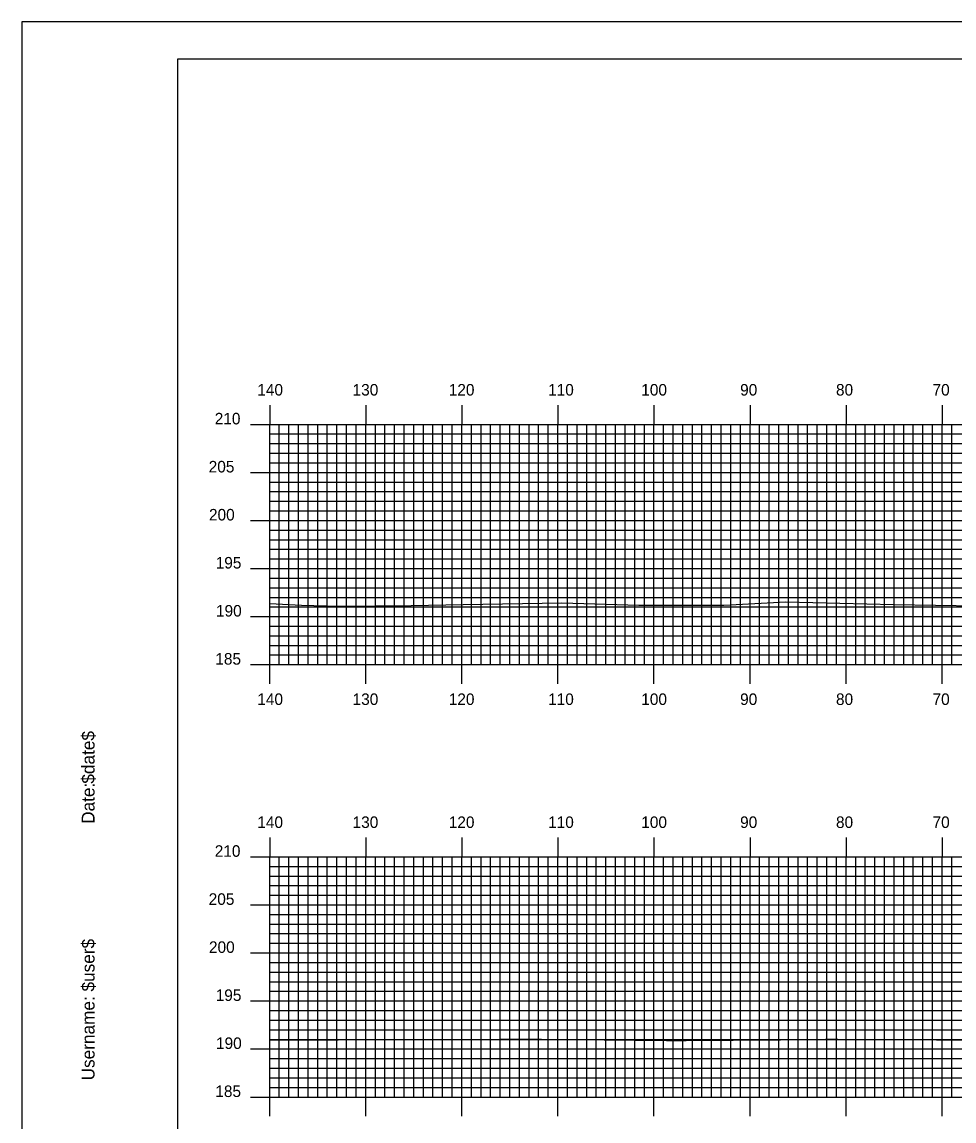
# Model space of a CAD drawing. Extents: x 1814915 to 1815259, y 442591 to 442811.
# Drawn here: x 1814915.2 to 1815012.3, y 442696.2 to 442810.5 of the extents above; entities that cross this region are included whole.
import ezdxf

# ---------------------------------------------------------------- set-up
doc = ezdxf.new("R2010")
doc.units = 0
for name, color, linetype in [('BORDER', 7, 'Continuous'), ('H_V ANNOTATION', 7, 'Continuous'), ('MAJOR', 7, 'Continuous'), ('MINOR', 7, 'Continuous'), ('PLOT BOUNDARY', 7, 'Continuous'), ('S_Roadway_Centerline', 7, 'Continuous')]:
    doc.layers.add(name, color=color, linetype=linetype)

msp = doc.modelspace()

# ---------------------------------------------------------------- linework, layer by layer
at = {"layer": 'BORDER'}
msp.add_lwpolyline([(1814931.42, 442596.67), (1815251.42, 442596.67), (1815251.42, 442806.67), (1814931.42, 442806.67)], close=True, dxfattribs=at)
at = {"layer": 'MAJOR'}
for p, q in [((1814941.02, 442770.67), (1814941.02, 442768.67)), ((1814951.02, 442770.67), (1814951.02, 442768.67)), ((1814961.02, 442770.67), (1814961.02, 442768.67)), ((1814971.02, 442770.67), (1814971.02, 442768.67)), ((1814981.02, 442770.67), (1814981.02, 442768.67)), ((1814991.02, 442770.67), (1814991.02, 442768.67)), ((1815001.02, 442770.67), (1815001.02, 442768.67)), ((1815011.02, 442770.67), (1815011.02, 442768.67)), ((1814939.02, 442768.67), (1814941.02, 442768.67)), ((1814941.02, 442768.67), (1815221.02, 442768.67)), ((1814941.02, 442743.67), (1814941.02, 442768.67)), ((1814941.02, 442743.67), (1814941.02, 442768.67)), ((1814941.02, 442768.67), (1815221.02, 442768.67)), ((1814951.02, 442743.67), (1814951.02, 442768.67)), ((1814961.02, 442743.67), (1814961.02, 442768.67)), ((1814971.02, 442743.67), (1814971.02, 442768.67)), ((1814981.02, 442743.67), (1814981.02, 442768.67)), ((1814991.02, 442743.67), (1814991.02, 442768.67)), ((1815001.02, 442743.67), (1815001.02, 442768.67)), ((1815011.02, 442743.67), (1815011.02, 442768.67)), ((1814939.02, 442763.67), (1814941.02, 442763.67)), ((1814941.02, 442763.67), (1815221.02, 442763.67)), ((1814939.02, 442758.67), (1814941.02, 442758.67)), ((1814941.02, 442758.67), (1815221.02, 442758.67)), ((1814939.02, 442753.67), (1814941.02, 442753.67)), ((1814941.02, 442753.67), (1815221.02, 442753.67)), ((1814939.02, 442748.67), (1814941.02, 442748.67)), ((1814941.02, 442748.67), (1815221.02, 442748.67)), ((1814939.02, 442743.67), (1814941.02, 442743.67)), ((1814941.02, 442743.67), (1815221.02, 442743.67)), ((1814941.02, 442743.67), (1815221.02, 442743.67)), ((1814941.02, 442741.66), (1814941.02, 442743.67)), ((1814951.02, 442741.66), (1814951.02, 442743.67)), ((1814961.02, 442741.66), (1814961.02, 442743.67)), ((1814971.02, 442741.66), (1814971.02, 442743.67)), ((1814981.02, 442741.66), (1814981.02, 442743.67)), ((1814991.02, 442741.66), (1814991.02, 442743.67)), ((1815001.02, 442741.66), (1815001.02, 442743.67)), ((1815011.02, 442741.66), (1815011.02, 442743.67)), ((1814941.02, 442725.67), (1814941.02, 442723.67)), ((1814951.02, 442725.67), (1814951.02, 442723.67)), ((1814961.02, 442725.67), (1814961.02, 442723.67)), ((1814971.02, 442725.67), (1814971.02, 442723.67)), ((1814981.02, 442725.67), (1814981.02, 442723.67)), ((1814991.02, 442725.67), (1814991.02, 442723.67)), ((1815001.02, 442725.67), (1815001.02, 442723.67)), ((1815011.02, 442725.67), (1815011.02, 442723.67)), ((1814939.02, 442723.67), (1814941.02, 442723.67)), ((1814941.02, 442723.67), (1815221.02, 442723.67)), ((1814941.02, 442698.67), (1814941.02, 442723.67)), ((1814941.02, 442698.67), (1814941.02, 442723.67)), ((1814941.02, 442723.67), (1815221.02, 442723.67)), ((1814951.02, 442698.67), (1814951.02, 442723.67)), ((1814961.02, 442698.67), (1814961.02, 442723.67)), ((1814971.02, 442698.67), (1814971.02, 442723.67)), ((1814981.02, 442698.67), (1814981.02, 442723.67)), ((1814991.02, 442698.67), (1814991.02, 442723.67)), ((1815001.02, 442698.67), (1815001.02, 442723.67)), ((1815011.02, 442698.67), (1815011.02, 442723.67)), ((1814939.02, 442718.67), (1814941.02, 442718.67)), ((1814941.02, 442718.67), (1815221.02, 442718.67)), ((1814939.02, 442713.67), (1814941.02, 442713.67)), ((1814941.02, 442713.67), (1815221.02, 442713.67)), ((1814939.02, 442708.67), (1814941.02, 442708.67)), ((1814941.02, 442708.67), (1815221.02, 442708.67)), ((1814939.02, 442703.67), (1814941.02, 442703.67)), ((1814941.02, 442703.67), (1815221.02, 442703.67)), ((1814939.02, 442698.67), (1814941.02, 442698.67)), ((1814941.02, 442698.67), (1815221.02, 442698.67)), ((1814941.02, 442698.67), (1815221.02, 442698.67)), ((1814941.02, 442696.66), (1814941.02, 442698.67)), ((1814951.02, 442696.66), (1814951.02, 442698.67)), ((1814961.02, 442696.66), (1814961.02, 442698.67)), ((1814971.02, 442696.66), (1814971.02, 442698.67)), ((1814981.02, 442696.66), (1814981.02, 442698.67)), ((1814991.02, 442696.66), (1814991.02, 442698.67)), ((1815001.02, 442696.66), (1815001.02, 442698.67)), ((1815011.02, 442696.66), (1815011.02, 442698.67))]:
    msp.add_line(p, q, dxfattribs=at)
at = {"layer": 'MINOR'}
for p, q in [((1814941.02, 442743.67), (1814941.02, 442768.67)), ((1814941.02, 442767.67), (1815221.02, 442767.67)), ((1814941.02, 442767.67), (1814943.02, 442767.67)), ((1814942.02, 442743.67), (1814942.02, 442768.67)), ((1814943.02, 442743.67), (1814943.02, 442768.67)), ((1814944.02, 442743.67), (1814944.02, 442768.67)), ((1814945.02, 442743.67), (1814945.02, 442768.67)), ((1814946.02, 442743.67), (1814946.02, 442768.67)), ((1814947.02, 442743.67), (1814947.02, 442768.67)), ((1814948.02, 442743.67), (1814948.02, 442768.67)), ((1814949.02, 442743.67), (1814949.02, 442768.67)), ((1814950.02, 442743.67), (1814950.02, 442768.67)), ((1814952.02, 442743.67), (1814952.02, 442768.67)), ((1814953.02, 442743.67), (1814953.02, 442768.67)), ((1814954.02, 442743.67), (1814954.02, 442768.67)), ((1814955.02, 442743.67), (1814955.02, 442768.67)), ((1814956.02, 442743.67), (1814956.02, 442768.67)), ((1814957.02, 442743.67), (1814957.02, 442768.67)), ((1814958.02, 442743.67), (1814958.02, 442768.67)), ((1814959.02, 442743.67), (1814959.02, 442768.67)), ((1814960.02, 442743.67), (1814960.02, 442768.67)), ((1814962.02, 442743.67), (1814962.02, 442768.67)), ((1814963.02, 442743.67), (1814963.02, 442768.67)), ((1814964.02, 442743.67), (1814964.02, 442768.67)), ((1814965.02, 442743.67), (1814965.02, 442768.67)), ((1814966.02, 442743.67), (1814966.02, 442768.67)), ((1814967.02, 442743.67), (1814967.02, 442768.67)), ((1814968.02, 442743.67), (1814968.02, 442768.67)), ((1814969.02, 442743.67), (1814969.02, 442768.67)), ((1814970.02, 442743.67), (1814970.02, 442768.67)), ((1814972.02, 442743.67), (1814972.02, 442768.67)), ((1814973.02, 442743.67), (1814973.02, 442768.67)), ((1814974.02, 442743.67), (1814974.02, 442768.67)), ((1814975.02, 442743.67), (1814975.02, 442768.67)), ((1814976.02, 442743.67), (1814976.02, 442768.67)), ((1814977.02, 442743.67), (1814977.02, 442768.67)), ((1814978.02, 442743.67), (1814978.02, 442768.67)), ((1814979.02, 442743.67), (1814979.02, 442768.67)), ((1814980.02, 442743.67), (1814980.02, 442768.67)), ((1814982.02, 442743.67), (1814982.02, 442768.67)), ((1814983.02, 442743.67), (1814983.02, 442768.67)), ((1814984.02, 442743.67), (1814984.02, 442768.67)), ((1814985.02, 442743.67), (1814985.02, 442768.67)), ((1814986.02, 442743.67), (1814986.02, 442768.67)), ((1814987.02, 442743.67), (1814987.02, 442768.67)), ((1814988.02, 442743.67), (1814988.02, 442768.67)), ((1814989.02, 442743.67), (1814989.02, 442768.67)), ((1814990.02, 442743.67), (1814990.02, 442768.67)), ((1814992.02, 442743.67), (1814992.02, 442768.67)), ((1814993.02, 442743.67), (1814993.02, 442768.67)), ((1814994.02, 442743.67), (1814994.02, 442768.67)), ((1814995.02, 442743.67), (1814995.02, 442768.67)), ((1814996.02, 442743.67), (1814996.02, 442768.67)), ((1814997.02, 442743.67), (1814997.02, 442768.67)), ((1814998.02, 442743.67), (1814998.02, 442768.67)), ((1814999.02, 442743.67), (1814999.02, 442768.67)), ((1815000.02, 442743.67), (1815000.02, 442768.67)), ((1815002.02, 442743.67), (1815002.02, 442768.67)), ((1815003.02, 442743.67), (1815003.02, 442768.67)), ((1815004.02, 442743.67), (1815004.02, 442768.67)), ((1815005.02, 442743.67), (1815005.02, 442768.67)), ((1815006.02, 442743.67), (1815006.02, 442768.67)), ((1815007.02, 442743.67), (1815007.02, 442768.67)), ((1815008.02, 442743.67), (1815008.02, 442768.67)), ((1815009.02, 442743.67), (1815009.02, 442768.67)), ((1815010.02, 442743.67), (1815010.02, 442768.67)), ((1815012.02, 442743.67), (1815012.02, 442768.67)), ((1814941.02, 442766.67), (1815221.02, 442766.67)), ((1814941.02, 442766.67), (1814943.02, 442766.67)), ((1814941.02, 442765.67), (1815221.02, 442765.67)), ((1814941.02, 442765.67), (1814943.02, 442765.67)), ((1814941.02, 442764.67), (1815221.02, 442764.67)), ((1814941.02, 442764.67), (1814943.02, 442764.67)), ((1814941.02, 442762.67), (1815221.02, 442762.67)), ((1814941.02, 442762.67), (1814943.02, 442762.67)), ((1814941.02, 442761.67), (1815221.02, 442761.67)), ((1814941.02, 442761.67), (1814943.02, 442761.67)), ((1814941.02, 442760.67), (1815221.02, 442760.67)), ((1814941.02, 442760.67), (1814943.02, 442760.67)), ((1814941.02, 442759.67), (1815221.02, 442759.67)), ((1814941.02, 442759.67), (1814943.02, 442759.67)), ((1814941.02, 442757.67), (1815221.02, 442757.67)), ((1814941.02, 442757.67), (1814943.02, 442757.67)), ((1814941.02, 442756.67), (1815221.02, 442756.67)), ((1814941.02, 442756.67), (1814943.02, 442756.67)), ((1814941.02, 442755.67), (1815221.02, 442755.67)), ((1814941.02, 442755.67), (1814943.02, 442755.67)), ((1814941.02, 442754.67), (1815221.02, 442754.67)), ((1814941.02, 442754.67), (1814943.02, 442754.67)), ((1814941.02, 442752.67), (1815221.02, 442752.67)), ((1814941.02, 442752.67), (1814943.02, 442752.67)), ((1814941.02, 442751.67), (1815221.02, 442751.67)), ((1814941.02, 442751.67), (1814943.02, 442751.67)), ((1814941.02, 442750.67), (1815221.02, 442750.67)), ((1814941.02, 442750.67), (1814943.02, 442750.67)), ((1814941.02, 442749.67), (1815221.02, 442749.67)), ((1814941.02, 442749.67), (1814943.02, 442749.67)), ((1814941.02, 442747.67), (1815221.02, 442747.67)), ((1814941.02, 442747.67), (1814943.02, 442747.67)), ((1814941.02, 442746.67), (1815221.02, 442746.67)), ((1814941.02, 442746.67), (1814943.02, 442746.67)), ((1814941.02, 442745.67), (1815221.02, 442745.67)), ((1814941.02, 442745.67), (1814943.02, 442745.67)), ((1814941.02, 442744.67), (1815221.02, 442744.67)), ((1814941.02, 442744.67), (1814943.02, 442744.67)), ((1814942.02, 442698.67), (1814942.02, 442723.67)), ((1814943.02, 442698.67), (1814943.02, 442723.67)), ((1814944.02, 442698.67), (1814944.02, 442723.67)), ((1814945.02, 442698.67), (1814945.02, 442723.67)), ((1814946.02, 442698.67), (1814946.02, 442723.67)), ((1814947.02, 442698.67), (1814947.02, 442723.67)), ((1814948.02, 442698.67), (1814948.02, 442723.67)), ((1814949.02, 442698.67), (1814949.02, 442723.67)), ((1814950.02, 442698.67), (1814950.02, 442723.67)), ((1814952.02, 442698.67), (1814952.02, 442723.67)), ((1814953.02, 442698.67), (1814953.02, 442723.67)), ((1814954.02, 442698.67), (1814954.02, 442723.67)), ((1814955.02, 442698.67), (1814955.02, 442723.67)), ((1814956.02, 442698.67), (1814956.02, 442723.67)), ((1814957.02, 442698.67), (1814957.02, 442723.67)), ((1814958.02, 442698.67), (1814958.02, 442723.67)), ((1814959.02, 442698.67), (1814959.02, 442723.67)), ((1814960.02, 442698.67), (1814960.02, 442723.67)), ((1814962.02, 442698.67), (1814962.02, 442723.67)), ((1814963.02, 442698.67), (1814963.02, 442723.67)), ((1814964.02, 442698.67), (1814964.02, 442723.67)), ((1814965.02, 442698.67), (1814965.02, 442723.67)), ((1814966.02, 442698.67), (1814966.02, 442723.67)), ((1814967.02, 442698.67), (1814967.02, 442723.67)), ((1814968.02, 442698.67), (1814968.02, 442723.67)), ((1814969.02, 442698.67), (1814969.02, 442723.67)), ((1814970.02, 442698.67), (1814970.02, 442723.67)), ((1814972.02, 442698.67), (1814972.02, 442723.67)), ((1814973.02, 442698.67), (1814973.02, 442723.67)), ((1814974.02, 442698.67), (1814974.02, 442723.67)), ((1814975.02, 442698.67), (1814975.02, 442723.67)), ((1814976.02, 442698.67), (1814976.02, 442723.67)), ((1814977.02, 442698.67), (1814977.02, 442723.67)), ((1814978.02, 442698.67), (1814978.02, 442723.67)), ((1814979.02, 442698.67), (1814979.02, 442723.67)), ((1814980.02, 442698.67), (1814980.02, 442723.67)), ((1814982.02, 442698.67), (1814982.02, 442723.67)), ((1814983.02, 442698.67), (1814983.02, 442723.67)), ((1814984.02, 442698.67), (1814984.02, 442723.67)), ((1814985.02, 442698.67), (1814985.02, 442723.67)), ((1814986.02, 442698.67), (1814986.02, 442723.67)), ((1814987.02, 442698.67), (1814987.02, 442723.67)), ((1814988.02, 442698.67), (1814988.02, 442723.67)), ((1814989.02, 442698.67), (1814989.02, 442723.67)), ((1814990.02, 442698.67), (1814990.02, 442723.67)), ((1814992.02, 442698.67), (1814992.02, 442723.67)), ((1814993.02, 442698.67), (1814993.02, 442723.67)), ((1814994.02, 442698.67), (1814994.02, 442723.67)), ((1814995.02, 442698.67), (1814995.02, 442723.67)), ((1814996.02, 442698.67), (1814996.02, 442723.67)), ((1814997.02, 442698.67), (1814997.02, 442723.67)), ((1814998.02, 442698.67), (1814998.02, 442723.67)), ((1814999.02, 442698.67), (1814999.02, 442723.67)), ((1815000.02, 442698.67), (1815000.02, 442723.67)), ((1815002.02, 442698.67), (1815002.02, 442723.67)), ((1815003.02, 442698.67), (1815003.02, 442723.67)), ((1815004.02, 442698.67), (1815004.02, 442723.67)), ((1815005.02, 442698.67), (1815005.02, 442723.67)), ((1815006.02, 442698.67), (1815006.02, 442723.67)), ((1815007.02, 442698.67), (1815007.02, 442723.67)), ((1815008.02, 442698.67), (1815008.02, 442723.67)), ((1815009.02, 442698.67), (1815009.02, 442723.67)), ((1815010.02, 442698.67), (1815010.02, 442723.67)), ((1815012.02, 442698.67), (1815012.02, 442723.67)), ((1814941.02, 442722.67), (1815221.02, 442722.67)), ((1814941.02, 442722.67), (1814943.02, 442722.67)), ((1814941.02, 442721.67), (1815221.02, 442721.67)), ((1814941.02, 442721.67), (1814943.02, 442721.67)), ((1814941.02, 442720.67), (1815221.02, 442720.67)), ((1814941.02, 442720.67), (1814943.02, 442720.67)), ((1814941.02, 442719.67), (1815221.02, 442719.67)), ((1814941.02, 442719.67), (1814943.02, 442719.67)), ((1814941.02, 442717.67), (1815221.02, 442717.67)), ((1814941.02, 442717.67), (1814943.02, 442717.67)), ((1814941.02, 442716.67), (1815221.02, 442716.67)), ((1814941.02, 442716.67), (1814943.02, 442716.67)), ((1814941.02, 442715.67), (1815221.02, 442715.67)), ((1814941.02, 442715.67), (1814943.02, 442715.67)), ((1814941.02, 442714.67), (1815221.02, 442714.67)), ((1814941.02, 442714.67), (1814943.02, 442714.67)), ((1814941.02, 442712.67), (1815221.02, 442712.67)), ((1814941.02, 442712.67), (1814943.02, 442712.67)), ((1814941.02, 442711.67), (1815221.02, 442711.67)), ((1814941.02, 442711.67), (1814943.02, 442711.67)), ((1814941.02, 442710.67), (1815221.02, 442710.67)), ((1814941.02, 442710.67), (1814943.02, 442710.67)), ((1814941.02, 442709.67), (1815221.02, 442709.67)), ((1814941.02, 442709.67), (1814943.02, 442709.67)), ((1814941.02, 442707.67), (1815221.02, 442707.67)), ((1814941.02, 442707.67), (1814943.02, 442707.67)), ((1814941.02, 442706.67), (1815221.02, 442706.67)), ((1814941.02, 442706.67), (1814943.02, 442706.67)), ((1814941.02, 442705.67), (1815221.02, 442705.67)), ((1814941.02, 442705.67), (1814943.02, 442705.67)), ((1814941.02, 442704.67), (1815221.02, 442704.67)), ((1814941.02, 442704.67), (1814943.02, 442704.67)), ((1814941.02, 442702.67), (1815221.02, 442702.67)), ((1814941.02, 442702.67), (1814943.02, 442702.67)), ((1814941.02, 442701.67), (1815221.02, 442701.67)), ((1814941.02, 442701.67), (1814943.02, 442701.67)), ((1814941.02, 442700.67), (1815221.02, 442700.67)), ((1814941.02, 442700.67), (1814943.02, 442700.67)), ((1814941.02, 442699.67), (1815221.02, 442699.67)), ((1814941.02, 442699.67), (1814943.02, 442699.67))]:
    msp.add_line(p, q, dxfattribs=at)
at = {"layer": 'PLOT BOUNDARY'}
msp.add_lwpolyline([(1814915.23, 442590.55), (1815255.23, 442590.55), (1815255.23, 442810.55), (1814915.23, 442810.55)], close=True, dxfattribs=at)
at = {"layer": 'S_Roadway_Centerline'}
for points in [[(1814941.02, 442750.03), (1814944.34, 442749.87), (1814948.23, 442749.76), (1814955.76, 442749.82), (1814961.16, 442749.91), (1814971.42, 442750.09), (1814979.46, 442749.85), (1814988.28, 442749.87), (1814994.74, 442750.19), (1815005.99, 442749.91), (1815019, 442749.73)], [(1814941.02, 442704.62), (1814942.98, 442704.62), (1814948.15, 442704.61), (1814956.73, 442704.67), (1814965.06, 442704.69), (1814969.33, 442704.7), (1814982.34, 442704.55), (1814984.37, 442704.55), (1814994.19, 442704.63), (1814998.89, 442704.7), (1815000.17, 442704.68), (1815015.58, 442704.58)]]:
    msp.add_lwpolyline(points, dxfattribs=at)

# ---------------------------------------------------------------- texts
at = {"layer": 'BORDER'}
for s, p in [('$date$', (1814922.79, 442731.28)), ('Date:', (1814922.79, 442727.1)), ('$user$', (1814922.79, 442709.65)), ('Username:', (1814922.79, 442700.4))]:
    msp.add_text(s, height=1.339, rotation=90, dxfattribs=at).set_placement(p)
at = {"layer": 'H_V ANNOTATION'}
for s, p in [('140', (1814939.73, 442771.67)), ('130', (1814949.65, 442771.67)), ('120', (1814959.66, 442771.67)), ('110', (1814970, 442771.67)), ('100', (1814979.7, 442771.67)), ('90', (1814989.99, 442771.67)), ('80', (1814999.97, 442771.67)), ('70', (1815010.02, 442771.67)), ('210', (1814935.3, 442768.67)), ('205', (1814934.67, 442763.67)), ('200', (1814934.7, 442758.67)), ('195', (1814935.4, 442753.67)), ('190', (1814935.43, 442748.67)), ('185', (1814935.36, 442743.67)), ('140', (1814939.73, 442739.47)), ('130', (1814949.65, 442739.47)), ('120', (1814959.66, 442739.47)), ('110', (1814970, 442739.47)), ('100', (1814979.7, 442739.47)), ('90', (1814989.99, 442739.47)), ('80', (1814999.97, 442739.47)), ('70', (1815010.02, 442739.47)), ('140', (1814939.73, 442726.67)), ('130', (1814949.65, 442726.67)), ('120', (1814959.66, 442726.67)), ('110', (1814970, 442726.67)), ('100', (1814979.7, 442726.67)), ('90', (1814989.99, 442726.67)), ('80', (1814999.97, 442726.67)), ('70', (1815010.02, 442726.67)), ('210', (1814935.3, 442723.67)), ('205', (1814934.67, 442718.67)), ('200', (1814934.7, 442713.67)), ('195', (1814935.4, 442708.67)), ('190', (1814935.43, 442703.67)), ('185', (1814935.36, 442698.67))]:
    msp.add_text(s, height=1.2, dxfattribs=at).set_placement(p)
at = {"layer": 'MAJOR'}
for p in [(1814941.01, 442743.67), (1814941.01, 442698.67)]:
    msp.add_text('-', height=0.012, dxfattribs=at).set_placement(p)

doc.saveas('drawing.dxf')
